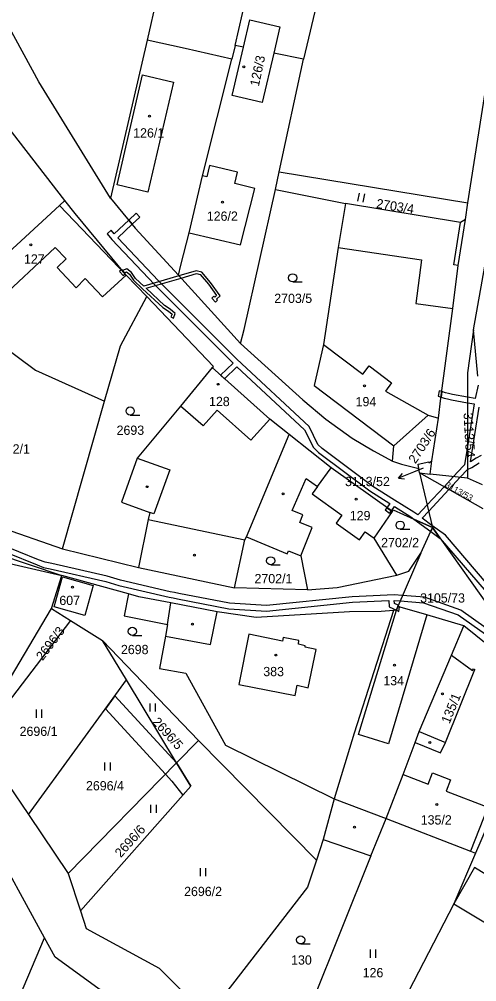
# Model space of a CAD drawing. Extents: x -776734 to -748832, y -1118122 to -976986.
# Drawn here: x -753561.2 to -753477.4, y -1115490.8 to -1115314.3 of the extents above; entities that cross this region are included whole.
import ezdxf

# ---------------------------------------------------------------- set-up
doc = ezdxf.new("R2010")
doc.units = 0
for name, color, linetype in [('KM_Hranice parcel', 7, 'Continuous'), ('KM_Parcelní čísla', 7, 'Continuous'), ('KM_Pop  PČ popisy', 7, 'Continuous'), ('KM_Vnitřní kresba', 7, 'Continuous'), ('KM_Věcná břemena k části', 7, 'Continuous'), ('KM_Značky budov', 7, 'Continuous'), ('KM_Značky kultur', 7, 'Continuous')]:
    doc.layers.add(name, color=color, linetype=linetype)

msp = doc.modelspace()

# ---------------------------------------------------------------- linework, layer by layer
at = {"layer": 'KM_Hranice parcel'}
for p, q in [((-753494.55, -1115260.42), (-753509.14, -1115321.59)), ((-753534.03, -1115301.72), (-753537.81, -1115318.08)), ((-753521.68, -1115319.09), (-753518.64, -1115305.9)), ((-753537.81, -1115318.08), (-753544.49, -1115347.06)), ((-753521.68, -1115319.09), (-753522.26, -1115321.6)), ((-753520.11, -1115319.4), (-753521.68, -1115319.09)), ((-753509.14, -1115321.59), (-753514.58, -1115320.51)), ((-753513.56, -1115342.25), (-753509.14, -1115321.59)), ((-753552.86, -1115347.49), (-753563.54, -1115333.73)), ((-753514.28, -1115345.47), (-753513.56, -1115342.25)), ((-753513.56, -1115342.25), (-753478.97, -1115347.96)), ((-753514.28, -1115345.47), (-753501.45, -1115348.08)), ((-753479.45, -1115351.02), (-753478.97, -1115347.96)), ((-753532.07, -1115361.23), (-753520.68, -1115373.73)), ((-753477.15, -1115379.74), (-753477.94, -1115371.21)), ((-753553.34, -1115411.39), (-753545.6, -1115384.35)), ((-753485.61, -1115395.25), (-753484.36, -1115387.44)), ((-753519.6, -1115409.22), (-753511.75, -1115390.42)), ((-753492.78, -1115395.32), (-753492.54, -1115392.5)), ((-753485.88, -1115397.69), (-753485.61, -1115395.25)), ((-753487.83, -1115397.48), (-753488, -1115396.69)), ((-753476.16, -1115404.08), (-753487.83, -1115397.48)), ((-753487.83, -1115397.48), (-753485.47, -1115407.51)), ((-753487.83, -1115397.48), (-753485.88, -1115397.69)), ((-753479.06, -1115398.42), (-753485.88, -1115397.69)), ((-753476.33, -1115399.68), (-753479.06, -1115398.42)), ((-753579.45, -1115402.39), (-753553.34, -1115411.39)), ((-753487.6, -1115412.22), (-753485.47, -1115407.51)), ((-753485.47, -1115407.51), (-753462.43, -1115440.03)), ((-753553.34, -1115411.39), (-753539.41, -1115414.86)), ((-753487.6, -1115412.22), (-753491.84, -1115421.96)), ((-753539.41, -1115414.86), (-753521.75, -1115418.59)), ((-753555.31, -1115422.38), (-753553.41, -1115416.31)), ((-753541.23, -1115419.66), (-753553.41, -1115416.31)), ((-753508.4, -1115418.91), (-753521.75, -1115418.59)), ((-753573.4, -1115452.82), (-753555.31, -1115422.38)), ((-753555.31, -1115422.38), (-753551.86, -1115424.53)), ((-753551.86, -1115424.53), (-753573.4, -1115452.82)), ((-753551.86, -1115424.53), (-753545.96, -1115428.2)), ((-753545.96, -1115428.2), (-753528.39, -1115446.57)), ((-753541.58, -1115435.46), (-753545.96, -1115428.2)), ((-753559.56, -1115460.16), (-753541.58, -1115435.46)), ((-753532.4, -1115450.66), (-753541.58, -1115435.46)), ((-753528.39, -1115446.57), (-753532.4, -1115450.66)), ((-753528.39, -1115446.57), (-753506.76, -1115468.51)), ((-753552.28, -1115470.97), (-753532.4, -1115450.66)), ((-753493.98, -1115460.87), (-753490.85, -1115452.81)), ((-753503.53, -1115457.28), (-753505.53, -1115464.7)), ((-753472.81, -1115456.07), (-753477.57, -1115467.24)), ((-753559.56, -1115460.16), (-753552.28, -1115470.97)), ((-753496.75, -1115467.75), (-753493.98, -1115460.87)), ((-753493.98, -1115460.87), (-753478.52, -1115466.87)), ((-753505.53, -1115464.7), (-753506.76, -1115468.51)), ((-753505.53, -1115464.7), (-753496.75, -1115467.75)), ((-753496.75, -1115467.75), (-753512.5, -1115506.85)), ((-753477.57, -1115467.24), (-753481.53, -1115476.51)), ((-753478.52, -1115466.87), (-753477.57, -1115467.24)), ((-753552.28, -1115470.97), (-753550.04, -1115477.8))]:
    msp.add_line(p, q, dxfattribs=at)
for points in [[(-753478.97, -1115347.96), (-753475.82, -1115327.7), (-753463.72, -1115266.09)], [(-753477.94, -1115371.21), (-753474.76, -1115353.37), (-753470.21, -1115330.79), (-753463.62, -1115298.06)], [(-753544.49, -1115347.06), (-753557.63, -1115325.76), (-753565, -1115312.34), (-753567.23, -1115307.22)], [(-753520.11, -1115319.4), (-753518.94, -1115314.37), (-753513.45, -1115315.66), (-753514.58, -1115320.51)], [(-753522.26, -1115321.6), (-753530.82, -1115319.62), (-753537.81, -1115318.08)], [(-753514.58, -1115320.51), (-753516.68, -1115329.52), (-753522.18, -1115328.24), (-753520.11, -1115319.4)], [(-753532.07, -1115361.23), (-753531.62, -1115359.35), (-753530.09, -1115353.44), (-753527.63, -1115342.98), (-753522.26, -1115321.6)], [(-753520.68, -1115373.73), (-753519.99, -1115371.16), (-753514.28, -1115345.47)], [(-753552.86, -1115347.49), (-753553.87, -1115348.42), (-753569.57, -1115362.83), (-753566, -1115366.71), (-753568.91, -1115370.77), (-753558.29, -1115378.62), (-753545.6, -1115384.35)], [(-753537.86, -1115365.15), (-753541.62, -1115361.21), (-753550.98, -1115349.92), (-753552.86, -1115347.49)], [(-753544.49, -1115347.06), (-753539.97, -1115352.56), (-753532.07, -1115361.23)], [(-753501.45, -1115348.08), (-753502.76, -1115356.16), (-753505.45, -1115373.93), (-753507.15, -1115381.43), (-753492.54, -1115392.5)], [(-753479.45, -1115351.02), (-753480.35, -1115351.56), (-753501.45, -1115348.08)], [(-753484.36, -1115387.44), (-753483.92, -1115383.75), (-753481.77, -1115367.31), (-753480.76, -1115359.42), (-753479.45, -1115351.02)], [(-753545.6, -1115384.35), (-753542.7, -1115374.2), (-753537.86, -1115365.15)], [(-753525.85, -1115378.17), (-753525.61, -1115377.95), (-753537.86, -1115365.15)], [(-753477.94, -1115371.21), (-753479.06, -1115379.12), (-753479.06, -1115398.42)], [(-753520.68, -1115373.73), (-753509.27, -1115384.09), (-753505.01, -1115387.65), (-753500.21, -1115391.1), (-753496.31, -1115393.41), (-753492.78, -1115395.32)], [(-753525.85, -1115378.17), (-753531.66, -1115385.21), (-753539.6, -1115394.76), (-753542.52, -1115402.85), (-753537.31, -1115404.73), (-753537.58, -1115406.03), (-753539.41, -1115414.86)], [(-753511.75, -1115390.42), (-753515.31, -1115387.6), (-753525.85, -1115378.17)], [(-753492.54, -1115392.5), (-753486.27, -1115386.86), (-753484.36, -1115387.44)], [(-753492.82, -1115404.58), (-753504.04, -1115396.56), (-753511.75, -1115390.42)], [(-753651.86, -1115392.67), (-753608.68, -1115400.67), (-753583.08, -1115406.36), (-753553.41, -1115416.31)], [(-753492.78, -1115395.32), (-753491.18, -1115395.87), (-753488, -1115396.69)], [(-753488, -1115396.69), (-753488.12, -1115395.88), (-753486.12, -1115395.44), (-753486.12, -1115395.63), (-753485.61, -1115395.25)], [(-753492.82, -1115404.58), (-753492.69, -1115404.23), (-753488.89, -1115405.96), (-753485.47, -1115407.51)], [(-753492, -1115416.25), (-753496.15, -1115409.46), (-753492.82, -1115404.58)], [(-753586.58, -1115407.5), (-753577.89, -1115410.7), (-753553.41, -1115416.31)], [(-753521.75, -1115418.59), (-753519.89, -1115409.76), (-753519.6, -1115409.22)], [(-753519.6, -1115409.22), (-753512.11, -1115412.33), (-753511.88, -1115411.76), (-753509.6, -1115412.71), (-753508.4, -1115418.91)], [(-753492, -1115416.25), (-753489.81, -1115415.49), (-753487.6, -1115412.22)], [(-753549.25, -1115423.64), (-753554.85, -1115422.08), (-753553.32, -1115416.55), (-753547.71, -1115418.12), (-753549.25, -1115423.64)], [(-753508.4, -1115418.91), (-753502.94, -1115418.52), (-753492, -1115416.25)], [(-753541.23, -1115419.66), (-753542.02, -1115423.71), (-753534.06, -1115425.3), (-753534.45, -1115427.43), (-753535.54, -1115433.34), (-753530.71, -1115434.22)], [(-753492.62, -1115422.71), (-753494.87, -1115422.91), (-753500.68, -1115422.99), (-753517.82, -1115423.99), (-753524.97, -1115422.94), (-753533.43, -1115421.34), (-753539.31, -1115420.19), (-753541.23, -1115419.66)], [(-753491.84, -1115421.96), (-753492.09, -1115422.69), (-753492.62, -1115422.71)], [(-753479.74, -1115425.52), (-753486.54, -1115423.5), (-753491.84, -1115421.96)], [(-753492.62, -1115422.71), (-753499.84, -1115445.21), (-753503.53, -1115457.28)], [(-753490.85, -1115452.81), (-753488.66, -1115446.94), (-753487.9, -1115444.91), (-753482.01, -1115430.9), (-753479.74, -1115425.52)], [(-753463.3, -1115439.24), (-753467.76, -1115435.2), (-753469.32, -1115433.93), (-753479.74, -1115425.52)], [(-753530.71, -1115434.22), (-753523.45, -1115447.42), (-753503.53, -1115457.28)], [(-753532.4, -1115450.66), (-753529.81, -1115454.95), (-753550.04, -1115477.8)], [(-753573.4, -1115452.82), (-753563.27, -1115454.65), (-753559.56, -1115460.16)], [(-753490.85, -1115452.81), (-753486.29, -1115454.58), (-753485.49, -1115452.52), (-753482.17, -1115453.81), (-753482.96, -1115455.87), (-753475.34, -1115458.82), (-753478.52, -1115466.87)], [(-753556.6, -1115482.75), (-753567.01, -1115463.79), (-753570.36, -1115463.2)], [(-753506.76, -1115468.51), (-753508.37, -1115473.5), (-753526.72, -1115497.21)], [(-753481.53, -1115476.51), (-753492.71, -1115498.03), (-753500.89, -1115513.62)], [(-753481.53, -1115476.51), (-753469.75, -1115483.63), (-753465.64, -1115486.23)], [(-753550.04, -1115477.8), (-753548.97, -1115481.08), (-753535.57, -1115488.33), (-753526.72, -1115497.21)], [(-753574.1, -1115527.68), (-753567.3, -1115507.72), (-753562.7, -1115497.21), (-753556.6, -1115482.75)], [(-753530.51, -1115503.85), (-753554.64, -1115486.34), (-753556.6, -1115482.75)]]:
    msp.add_lwpolyline(points, dxfattribs=at)
at = {"layer": 'KM_Pop  PČ popisy'}
for p, q in [((-753488.93, -1115397.33), (-753491.712, -1115398.454)), ((-753487.2, -1115396.64), (-753488.93, -1115397.33)), ((-753491.712, -1115398.454), (-753490.972, -1115397.615)), ((-753491.712, -1115398.454), (-753490.596, -1115398.543))]:
    msp.add_line(p, q, dxfattribs=at)
at = {"layer": 'KM_Vnitřní kresba'}
for p, q in [((-753543.31, -1115344.64), (-753538.63, -1115324.44)), ((-753538.63, -1115324.44), (-753532.95, -1115325.83)), ((-753532.95, -1115325.83), (-753537.67, -1115346)), ((-753526.35, -1115341.12), (-753526.83, -1115343.17)), ((-753521.23, -1115342.33), (-753526.35, -1115341.12)), ((-753521.72, -1115344.37), (-753521.23, -1115342.33)), ((-753526.83, -1115343.17), (-753527.63, -1115342.98)), ((-753537.67, -1115346), (-753543.31, -1115344.64)), ((-753518.04, -1115345.29), (-753521.72, -1115344.37)), ((-753520.7, -1115355.65), (-753518.04, -1115345.29)), ((-753541.62, -1115361.21), (-753553.87, -1115348.42)), ((-753481.55, -1115359.3), (-753480.35, -1115351.56)), ((-753530.09, -1115353.44), (-753520.7, -1115355.65)), ((-753554.66, -1115356.11), (-753566, -1115366.71)), ((-753552.64, -1115358.21), (-753554.66, -1115356.11)), ((-753502.76, -1115356.16), (-753487.5, -1115358.42)), ((-753554.31, -1115359.81), (-753552.64, -1115358.21)), ((-753487.5, -1115358.42), (-753488.52, -1115366.38)), ((-753550.81, -1115363.52), (-753554.31, -1115359.81)), ((-753480.76, -1115359.42), (-753481.55, -1115359.3)), ((-753549.15, -1115361.84), (-753550.81, -1115363.52)), ((-753545.96, -1115365.17), (-753549.15, -1115361.84)), ((-753541.62, -1115361.21), (-753545.96, -1115365.17)), ((-753488.52, -1115366.38), (-753481.77, -1115367.31)), ((-753505.45, -1115373.93), (-753498.22, -1115379.38)), ((-753498.22, -1115379.38), (-753497.06, -1115377.84)), ((-753497.06, -1115377.84), (-753492.96, -1115380.93)), ((-753492.96, -1115380.93), (-753494.12, -1115382.46)), ((-753494.12, -1115382.46), (-753486.27, -1115386.86)), ((-753527.5, -1115388.83), (-753531.66, -1115385.21)), ((-753524.95, -1115385.98), (-753527.5, -1115388.83)), ((-753518.79, -1115391.49), (-753524.95, -1115385.98)), ((-753515.31, -1115387.6), (-753518.79, -1115391.49)), ((-753539.6, -1115394.76), (-753533.64, -1115396.91)), ((-753533.64, -1115396.91), (-753536.56, -1115405)), ((-753506.55, -1115399.99), (-753504.04, -1115396.56)), ((-753511.18, -1115404.38), (-753508.62, -1115398.53)), ((-753508.62, -1115398.53), (-753506.55, -1115399.99)), ((-753506.55, -1115399.99), (-753507.53, -1115401.33)), ((-753507.53, -1115401.33), (-753502.08, -1115405.22)), ((-753509.22, -1115405.16), (-753511.18, -1115404.38)), ((-753537.58, -1115406.03), (-753519.89, -1115409.76)), ((-753536.56, -1115405), (-753537.31, -1115404.73)), ((-753509.8, -1115406.6), (-753509.22, -1115405.16)), ((-753502.08, -1115405.22), (-753503.13, -1115406.68)), ((-753507.53, -1115407.5), (-753509.8, -1115406.6)), ((-753509.6, -1115412.71), (-753507.53, -1115407.5)), ((-753503.13, -1115406.68), (-753498.84, -1115409.75)), ((-753498.84, -1115409.75), (-753497.79, -1115408.28)), ((-753497.79, -1115408.28), (-753496.15, -1115409.46)), ((-753534.06, -1115425.3), (-753533.43, -1115421.34)), ((-753526.18, -1115428.95), (-753524.97, -1115422.94)), ((-753499.03, -1115445.46), (-753492.09, -1115422.69)), ((-753486.54, -1115423.5), (-753493.56, -1115447.18)), ((-753519.13, -1115427.05), (-753520.96, -1115436.28)), ((-753512.98, -1115428.32), (-753519.13, -1115427.05)), ((-753534.45, -1115427.43), (-753526.18, -1115428.95)), ((-753512.84, -1115427.65), (-753512.98, -1115428.32)), ((-753509.97, -1115428.2), (-753512.84, -1115427.65)), ((-753510.06, -1115428.92), (-753509.97, -1115428.2)), ((-753508.81, -1115429.18), (-753510.06, -1115428.92)), ((-753508.81, -1115429.45), (-753508.81, -1115429.18)), ((-753506.8, -1115429.89), (-753508.81, -1115429.45)), ((-753508.25, -1115436.93), (-753506.8, -1115429.89)), ((-753482.01, -1115430.9), (-753478.11, -1115433.73)), ((-753483.11, -1115446.95), (-753477.73, -1115433.57)), ((-753478.11, -1115433.73), (-753477.97, -1115433.43)), ((-753477.97, -1115433.43), (-753477.73, -1115433.57)), ((-753520.96, -1115436.28), (-753510.66, -1115438.31)), ((-753510.66, -1115438.31), (-753510.27, -1115436.42)), ((-753510.27, -1115436.42), (-753508.25, -1115436.93)), ((-753487.9, -1115444.91), (-753483.11, -1115446.95)), ((-753493.56, -1115447.18), (-753499.03, -1115445.46)), ((-753503.53, -1115457.28), (-753493.98, -1115460.87)), ((-753477.78, -1115469.85), (-753481.53, -1115476.51)), ((-753469.66, -1115474.87), (-753477.78, -1115469.85))]:
    msp.add_line(p, q, dxfattribs=at)
msp.add_lwpolyline([(-753488.66, -1115446.94), (-753483.99, -1115448.83), (-753483.11, -1115446.95)], dxfattribs=at)
at = {"layer": 'KM_Věcná břemena k části'}
for points in [[(-753467.81, -1115426.82), (-753483.09, -1115408.89), (-753485.57, -1115407.1), (-753487.36, -1115405.81), (-753486.17, -1115404.53), (-753482.45, -1115400.52), (-753483.35, -1115400.01), (-753486.45, -1115403.35), (-753488.16, -1115405.2), (-753488.88, -1115404.71), (-753492.43, -1115402.46), (-753496.39, -1115399.97), (-753505.72, -1115392.99), (-753506.49, -1115392.25), (-753508.11, -1115388.98), (-753521.36, -1115376.63), (-753535.7, -1115362.25), (-753543.2, -1115354.36), (-753540.54, -1115351.87), (-753541.17, -1115351.1), (-753543.86, -1115353.62), (-753544.38, -1115352.98), (-753545.15, -1115353.61), (-753544.27, -1115354.68), (-753536.42, -1115362.94), (-753522.04, -1115377.34), (-753524.33, -1115379.53), (-753523.59, -1115380.2), (-753521.34, -1115378.01), (-753508.93, -1115389.58), (-753507.31, -1115392.85), (-753506.36, -1115393.75), (-753496.95, -1115400.8), (-753493.29, -1115403.12), (-753493.83, -1115403.86), (-753493.01, -1115404.44), (-753492.43, -1115403.67), (-753489.45, -1115405.54), (-753488.89, -1115405.96), (-753485.47, -1115407.51), (-753484.06, -1115409.49), (-753468.73, -1115427.29)], [(-753477.08, -1115381.37), (-753477.67, -1115383.83), (-753479.06, -1115383.57), (-753481.8, -1115383.07), (-753482.54, -1115382.92), (-753483.07, -1115382.79), (-753483.76, -1115382.56), (-753483.9, -1115383.58), (-753483.33, -1115383.75), (-753482.75, -1115383.9), (-753481.97, -1115384.06), (-753479.06, -1115384.61), (-753477.85, -1115384.84), (-753479.06, -1115392.61), (-753479.59, -1115396.01), (-753479.87, -1115396.25), (-753481.63, -1115398.15), (-753483.35, -1115400.01), (-753482.45, -1115400.52), (-753480.37, -1115398.28), (-753479.06, -1115396.88), (-753478.23, -1115396.46), (-753476.94, -1115395.64)], [(-753476.55, -1115394.31), (-753477.45, -1115394.77), (-753478.48, -1115395.43), (-753476.92, -1115385.41)], [(-753707.93, -1115412.58), (-753692.88, -1115403.03), (-753672.3, -1115391), (-753670.42, -1115390.26), (-753667.3, -1115389.72), (-753665.33, -1115389.38), (-753657.47, -1115390.54), (-753637.12, -1115393.67), (-753615.92, -1115397.74), (-753584.38, -1115404.91), (-753568.93, -1115409.94), (-753557.98, -1115414.37), (-753556.79, -1115414.83), (-753555.58, -1115415.08), (-753545.39, -1115417.39), (-753542.98, -1115418.14), (-753533.73, -1115420.28)], [(-753467.93, -1115435.06), (-753466.9, -1115433.72), (-753469.12, -1115430.59), (-753480.28, -1115422.64), (-753486.93, -1115420.3), (-753490.97, -1115419.97), (-753492.53, -1115419.84), (-753500.22, -1115420.21), (-753515.93, -1115421.83), (-753522.7, -1115421.39), (-753532, -1115419.63), (-753532.79, -1115419.44), (-753533.55, -1115419.29), (-753542.71, -1115417.17), (-753545.13, -1115416.42), (-753555.3, -1115414.12), (-753556.5, -1115413.87), (-753557.7, -1115413.4), (-753568.59, -1115409)], [(-753533.73, -1115420.28), (-753533, -1115420.42), (-753532.22, -1115420.61), (-753522.82, -1115422.39), (-753515.91, -1115422.83), (-753500.14, -1115421.21), (-753493.47, -1115420.88), (-753493.39, -1115422.08), (-753492.09, -1115422.69), (-753491.84, -1115421.96), (-753491.74, -1115421.73), (-753492.43, -1115421.42), (-753492.48, -1115420.89), (-753491.41, -1115420.97), (-753487.14, -1115421.29), (-753480.74, -1115423.54), (-753469.28, -1115431.67), (-753467.66, -1115433.03), (-753468.71, -1115434.42), (-753467.93, -1115435.06)]]:
    msp.add_lwpolyline(points, dxfattribs=at)
for points in [[(-753539.83, -1115349.84), (-753541.17, -1115351.1), (-753540.54, -1115351.87), (-753539.14, -1115350.57)], [(-753541.98, -1115360.78), (-753542.31, -1115360.38), (-753542.46, -1115360.19), (-753542.85, -1115360.52), (-753542.21, -1115361.28), (-753541.83, -1115360.96)], [(-753542.31, -1115360.38), (-753541.98, -1115360.78), (-753541.58, -1115360.62), (-753541.01, -1115361.04), (-753540.3, -1115362.11), (-753538.63, -1115363.69), (-753534.94, -1115367.15), (-753533.85, -1115367.83), (-753533.23, -1115368.37), (-753533.45, -1115368.87), (-753532.99, -1115369.07), (-753532.63, -1115368.23), (-753533.55, -1115367.43), (-753534.63, -1115366.75), (-753537.99, -1115363.6), (-753531.58, -1115361.77), (-753531.96, -1115361.35), (-753538.42, -1115363.21), (-753539.92, -1115361.79), (-753540.64, -1115360.7), (-753541.5, -1115360.06)], [(-753531.96, -1115361.35), (-753531.58, -1115361.77), (-753528.77, -1115360.91), (-753528.06, -1115361.08), (-753526.55, -1115362.86), (-753525.06, -1115364.94), (-753525.41, -1115365.25), (-753525.57, -1115365.07), (-753525.95, -1115365.41), (-753525.29, -1115366.15), (-753524.91, -1115365.81), (-753525.08, -1115365.62), (-753524.4, -1115365.02), (-753526.17, -1115362.54), (-753527.78, -1115360.64), (-753528.79, -1115360.39)], [(-753484.41, -1115383.42), (-753483.9, -1115383.58), (-753483.76, -1115382.56), (-753484.27, -1115382.4)], [(-753493.83, -1115403.86), (-753494.13, -1115404.27), (-753493.33, -1115404.87), (-753493.01, -1115404.44)], [(-753488.25, -1115406.44), (-753485.79, -1115408.23), (-753485.47, -1115407.51), (-753488.89, -1115405.96)], [(-753484.06, -1115409.49), (-753485.47, -1115407.51), (-753485.79, -1115408.23)], [(-753491.84, -1115421.96), (-753492.09, -1115422.69), (-753491.64, -1115422.91), (-753491.52, -1115422.05)], [(-753543.69, -1115438.36), (-753545.46, -1115440.79), (-753534.44, -1115452.75), (-753533.25, -1115454.05), (-753531.28, -1115456.62), (-753529.81, -1115454.95), (-753532.4, -1115450.66)]]:
    msp.add_lwpolyline(points, close=True, dxfattribs=at)
at = {"layer": 'KM_Značky budov'}
for centre in [(-753520.0768, -1115322.9992), (-753537.3768, -1115332.0492), (-753523.9968, -1115347.8292), (-753559.1068, -1115355.6292), (-753524.7668, -1115381.2292), (-753497.9368, -1115381.4992), (-753537.8068, -1115400.0092), (-753512.8768, -1115401.2992), (-753499.4468, -1115402.3192), (-753529.1368, -1115412.5792), (-753551.4868, -1115418.4592), (-753529.5068, -1115425.2492), (-753514.1968, -1115430.8892), (-753492.4568, -1115432.7292), (-753483.6668, -1115438.0192), (-753485.9768, -1115446.9492), (-753484.6668, -1115458.3192), (-753499.7568, -1115462.4492)]:
    msp.add_circle(centre, 0.175, dxfattribs=at)
at = {"layer": 'KM_Značky kultur'}
for p, q in [((-753499.143, -1115347.621), (-753498.883, -1115346.144)), ((-753498.157, -1115347.795), (-753497.897, -1115346.318)), ((-753511.103, -1115362.44), (-753509.353, -1115362.44)), ((-753540.913, -1115386.88), (-753539.163, -1115386.88)), ((-753491.403, -1115407.82), (-753489.653, -1115407.82)), ((-753515.133, -1115414.35), (-753513.383, -1115414.35)), ((-753540.503, -1115427.31), (-753538.753, -1115427.31)), ((-753558.111, -1115442.4), (-753558.111, -1115440.9)), ((-753557.11, -1115442.4), (-753557.11, -1115440.9)), ((-753537.261, -1115441.26), (-753537.261, -1115439.76)), ((-753536.26, -1115441.26), (-753536.26, -1115439.76)), ((-753545.531, -1115452.09), (-753545.531, -1115450.59)), ((-753544.53, -1115452.09), (-753544.53, -1115450.59)), ((-753537.091, -1115459.86), (-753537.091, -1115458.36)), ((-753536.09, -1115459.86), (-753536.09, -1115458.36)), ((-753528.011, -1115471.46), (-753528.011, -1115469.96)), ((-753527.01, -1115471.46), (-753527.01, -1115469.96)), ((-753509.633, -1115483.9), (-753507.883, -1115483.9)), ((-753496.861, -1115486.41), (-753496.861, -1115484.91)), ((-753495.86, -1115486.41), (-753495.86, -1115484.91))]:
    msp.add_line(p, q, dxfattribs=at)
for centre in [(-753511.1029, -1115361.6898), (-753540.9129, -1115386.1298), (-753491.4029, -1115407.0698), (-753515.1329, -1115413.5998), (-753540.5029, -1115426.5598), (-753509.6329, -1115483.1498)]:
    msp.add_circle(centre, 0.75, dxfattribs=at)

# ---------------------------------------------------------------- texts
at = {"layer": 'KM_Parcelní čísla'}
for s, height, rotation, p in [('126/3', 1.7, 78, (-753517.314, -1115326.673)), ('2703/4', 1.7, 351, (-753495.872, -1115348.859)), ('3113/54', 1.7, 273, (-753479.778, -1115386.474)), ('2703/6', 1.7, 57, (-753488.587, -1115395.912)), ('3113/53', 1.14, 331, (-753483.272, -1115400.024)), ('2696/3', 1.7, 53, (-753556.971, -1115432.041)), ('135/1', 1.7, 68, (-753482.357, -1115443.606)), ('2696/5', 1.7, 312, (-753536.951, -1115443.248)), ('2696/6', 1.7, 48, (-753542.628, -1115468.158))]:
    msp.add_text(s, height=height, rotation=rotation, dxfattribs=at).set_placement(p)
for s, p in [('126/1', (-753540.35, -1115335.96)), ('126/2', (-753526.86, -1115351.23)), ('127', (-753560.38, -1115359.09)), ('2703/5', (-753514.49, -1115366.31)), ('128', (-753526.45, -1115385.23)), ('194', (-753499.57, -1115385.26)), ('2693', (-753543.4, -1115390.5)), ('2692/1', (-753566.25, -1115393.93)), ('3113/52', (-753501.513, -1115399.908)), ('129', (-753500.64, -1115406.16)), ('2702/2', (-753494.89, -1115411.11)), ('2702/1', (-753518.11, -1115417.72)), ('607', (-753553.895, -1115421.72)), ('3105/73', (-753487.74, -1115421.27)), ('2698', (-753542.6, -1115430.73)), ('383', (-753516.5, -1115434.77)), ('134', (-753494.49, -1115436.45)), ('2696/1', (-753561.18, -1115445.73)), ('2696/4', (-753549.01, -1115455.72)), ('135/2', (-753487.63, -1115461.98)), ('2696/2', (-753531.02, -1115475.11)), ('130', (-753511.4, -1115487.68)), ('126', (-753498.28, -1115490))]:
    msp.add_text(s, height=1.7, dxfattribs=at).set_placement(p)

doc.saveas('drawing.dxf')
